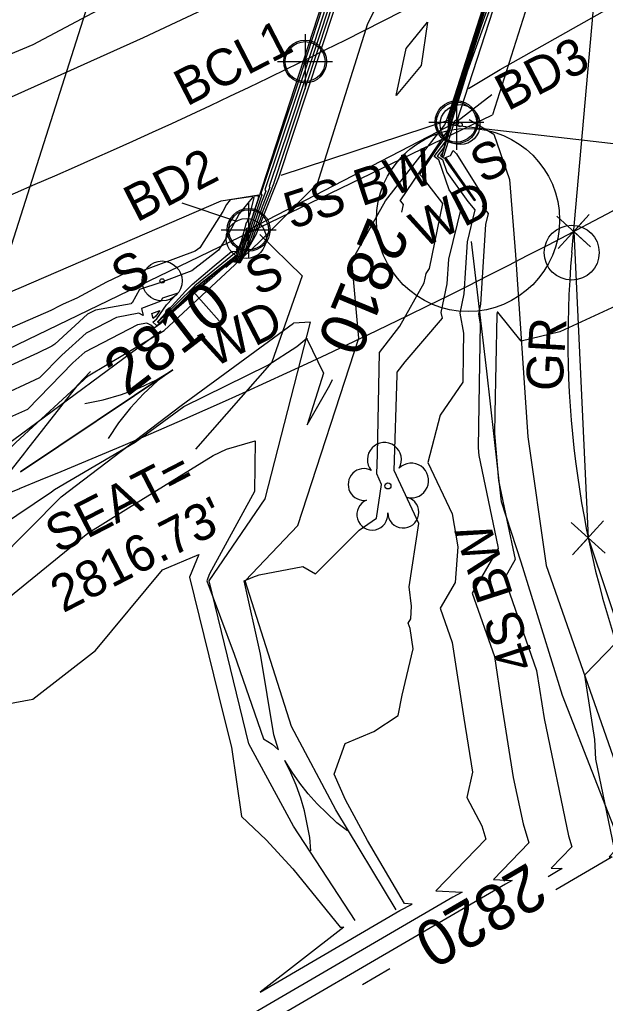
# Model space of a CAD drawing. Extents: x 1284446 to 1285480, y 969739 to 970628.
# Drawn here: x 1284857.4 to 1284921.4, y 970083.4 to 970190.8 of the extents above; entities that cross this region are included whole.
import ezdxf

# ---------------------------------------------------------------- set-up
doc = ezdxf.new("R2010")
doc.units = 0
for name, color, linetype in [('Cogo Default Point CELL', 7, 'Continuous'), ('Default', 7, 'Continuous'), ('Exist Horizontal Alignment', 7, 'Continuous'), ('Exist Horizontal Alignment Point', 7, 'Continuous'), ('Exist Hydro Jurisdictional Stream or Body of Water', 7, 'Continuous'), ('Exist Hydro River Flow Arrow CELL', 7, 'Continuous'), ('Exist Hydro Stream Flow Arrow CELL', 7, 'Continuous'), ('Exist Other Culture Fence Line', 7, 'Continuous'), ('Exist Other Culture Fence Line Text', 7, 'Continuous'), ('Exist Other Culture Located Object CELL', 7, 'Continuous'), ('Exist Other Culture Located Object Leader', 7, 'Continuous'), ('Exist Other Culture Located Object Text', 7, 'Continuous'), ('Exist Other Culture Sign CELL', 7, 'Continuous'), ('Exist Other Culture Sign Text', 7, 'Continuous'), ('Exist Property Corner CELL', 7, 'Continuous'), ('Exist Property Line', 7, 'Continuous'), ('Exist Right of Way Line', 7, 'Continuous'), ('Exist Roads EOP', 7, 'Continuous'), ('Exist Roads Soil', 7, 'Continuous'), ('Exist Roads Soil Text', 7, 'Continuous'), ('Exist Structure Major Bridge WW', 7, 'Continuous'), ('Exist Structure Major Bridge WW Leader', 7, 'Continuous'), ('Exist Structure Major Bridge WW Text', 7, 'Continuous'), ('Exist Structure Major Deck Tunnel Box Culvert', 7, 'Continuous'), ('Exist Structure Minor Head and End Wall', 7, 'Continuous'), ('Exist Vegetation Tree CELL', 7, 'Continuous')]:
    doc.layers.add(name, color=color, linetype=linetype)

msp = doc.modelspace()

# ---------------------------------------------------------------- linework, layer by layer
at = {"layer": 'Cogo Default Point CELL'}
for points in [[(1284888.59, 970189.26), (1284888.59, 970186.26)], [(1284885.59, 970186.26), (1284888.59, 970186.26)], [(1284888.59, 970186.26), (1284891.59, 970186.26)], [(1284888.59, 970186.26), (1284888.59, 970183.26)], [(1284905.12, 970182.64), (1284905.12, 970179.64)], [(1284902.12, 970179.64), (1284905.12, 970179.64)], [(1284905.12, 970179.64), (1284908.12, 970179.64)], [(1284905.12, 970179.64), (1284905.12, 970176.64)], [(1284882.42, 970170.89), (1284882.42, 970167.89)], [(1284879.42, 970167.89), (1284882.42, 970167.89)], [(1284882.42, 970167.89), (1284885.42, 970167.89)], [(1284882.42, 970167.89), (1284882.42, 970164.89)]]:
    msp.add_lwpolyline(points, dxfattribs=at)
for centre in [(1284888.59, 970186.26), (1284905.12, 970179.64), (1284882.42, 970167.89)]:
    msp.add_circle(centre, 2.34, dxfattribs=at)
at = {"layer": 'Default'}
for points in [[(1284899.15, 970169.83), (1284899.32, 970170.65), (1284899.03, 970171.02), (1284898.99, 970171.06), (1284903.87, 970178.3), (1284904.15, 970178.67), (1284904.24, 970178.96), (1284904.28, 970180.22), (1284904.39, 970180.56), (1284912.25, 970204.98)], [(1284911.74, 970201.12), (1284907.81, 970190.18), (1284905.23, 970182.15), (1284904.46, 970179.62), (1284904.44, 970179.21), (1284903.74, 970176.89), (1284903.02, 970175.95), (1284903.3, 970175.74), (1284903.58, 970175.58), (1284904.07, 970174.18), (1284906.37, 970170.99), (1284907.13, 970170.07), (1284906.29, 970166.6), (1284905.93, 970160.89), (1284905.49, 970158.78), (1284905.9, 970156.62), (1284905.85, 970154.4), (1284905.82, 970151.27), (1284903.33, 970147.65), (1284902.01, 970142.5), (1284904.66, 970136.9), (1284905.26, 970133.29), (1284904.97, 970129.39), (1284903.35, 970126.59), (1284904.66, 970122.84), (1284905.91, 970114.58), (1284906.86, 970108.69), (1284906.26, 970105.93), (1284907.88, 970102.82), (1284908.31, 970101.38), (1284902.87, 970095.74), (1284905.74, 970095.58), (1284904.71, 970095.03), (1284857.93, 970067.77)], [(1284856.22, 970127.75), (1284864.85, 970134.79), (1284870.66, 970138.38), (1284878.55, 970143.26), (1284880, 970143.94), (1284883.15, 970144.84), (1284883.05, 970139.32), (1284878.14, 970130.35), (1284877.86, 970129.58), (1284880.85, 970121.58), (1284884.03, 970112.32), (1284885, 970111.74), (1284885.68, 970111.11), (1284885.16, 970112.75), (1284883.72, 970121.57), (1284881.94, 970129.59), (1284882.9, 970129.97), (1284883.57, 970130.22), (1284888.34, 970131.13), (1284889.72, 970130.33), (1284894.51, 970135.09), (1284896.4, 970136.43), (1284896.95, 970140.1), (1284896.41, 970141.26), (1284896.48, 970143.35), (1284896.71, 970154.51), (1284898.92, 970157.37), (1284901.58, 970162.12), (1284901.82, 970163.13), (1284902.18, 970163.68), (1284903.64, 970170.75), (1284901.4, 970173.63), (1284901.12, 970173.94), (1284903.09, 970176.87), (1284904.01, 970178.07), (1284904.31, 970179.04), (1284904.34, 970180.02), (1284904.67, 970181.09), (1284910.77, 970200.05)], [(1284892.62, 970198.83), (1284888.83, 970187.06), (1284888.04, 970184.66), (1284883.74, 970171.87), (1284883.87, 970171.69), (1284883.75, 970171.38), (1284882.63, 970168.02), (1284882.57, 970167.88), (1284881.53, 970164.77), (1284881.39, 970164.52), (1284881.21, 970164.54), (1284881.15, 970164.55), (1284881.18, 970164.96), (1284881.59, 970166.18), (1284882.11, 970167.54), (1284882.26, 970168.07), (1284882.45, 970168.12), (1284883.44, 970171.1), (1284883.55, 970171.51), (1284883.38, 970171.62), (1284880.41, 970171.16), (1284880, 970170.65), (1284879.6, 970169.91), (1284877.09, 970165.93), (1284876.6, 970165.55), (1284870.45, 970163.26), (1284869.9, 970163.61), (1284866.9, 970162.18), (1284863.66, 970160.45), (1284862.16, 970159.79), (1284862.03, 970159.69), (1284861.8, 970159.58), (1284860.83, 970159.08), (1284851.5, 970155.03)], [(1284911.3, 970199.08), (1284906.34, 970185.25), (1284905.51, 970182.68), (1284904.51, 970179.42), (1284904.51, 970179.29), (1284903.6, 970176.3), (1284903.36, 970175.99), (1284903.45, 970175.92), (1284903.75, 970175.75), (1284903.82, 970175.73), (1284903.92, 970175.78), (1284904.48, 970176), (1284904.76, 970176.55), (1284905.12, 970176.2), (1284908.14, 970171.35), (1284908.18, 970171.1), (1284908.06, 970170.47), (1284907.93, 970170.46), (1284908.58, 970169.69), (1284908.29, 970168.49), (1284907.73, 970159.76), (1284907.51, 970158.7), (1284907.72, 970157.62), (1284907.59, 970151.12), (1284907.5, 970144.1), (1284907.57, 970143.27), (1284909.63, 970133.32), (1284909.67, 970133.12), (1284906.85, 970128.21), (1284909.26, 970121.32), (1284910.04, 970116.16), (1284911.33, 970108.11), (1284912.39, 970103.04), (1284913.02, 970100.96), (1284909.18, 970096.98), (1284911.2, 970096.86), (1284910.48, 970096.47), (1284873.73, 970075.07)], [(1284892.48, 970197.32), (1284889.57, 970188.3), (1284887.45, 970181.89), (1284884.21, 970172.25), (1284884.31, 970172.12), (1284883.82, 970170.9), (1284882.97, 970168.35), (1284882.75, 970167.79), (1284881.96, 970165.44), (1284881.41, 970164.45), (1284881.27, 970164.46), (1284881.03, 970164.52), (1284881.08, 970165.02), (1284877.43, 970162.18), (1284875.87, 970160.81), (1284872.68, 970157.68), (1284872.65, 970157.66), (1284872.51, 970157.82), (1284872.49, 970157.84), (1284872.52, 970157.87), (1284872.6, 970157.99), (1284875.53, 970161.2), (1284876.25, 970161.94), (1284878.67, 970163.96), (1284880.56, 970165.51), (1284881.08, 970165.57), (1284881.16, 970165.42), (1284881.64, 970166.65), (1284882.2, 970168.71), (1284882.27, 970168.73), (1284882.62, 970169.79), (1284883.03, 970171.41), (1284883.02, 970171.42), (1284882.8, 970171.39), (1284881.4, 970169.63), (1284880.01, 970167.06), (1284879.14, 970165.69), (1284876.22, 970163.41), (1284872.84, 970162.15), (1284870.5, 970161.39), (1284869.71, 970159.91), (1284869.59, 970159.86), (1284869.6, 970159.82), (1284869.58, 970159.83), (1284865.69, 970159.11), (1284864.84, 970158.67), (1284861.25, 970155.42), (1284860.92, 970155.18), (1284859.37, 970154.43), (1284853.43, 970151.74)], [(1284952.68, 970196.7), (1284945.69, 970190.22), (1284942.86, 970188.46), (1284935.48, 970181.51), (1284934.9, 970180.03), (1284930.07, 970174.35), (1284927.01, 970165.95), (1284926.01, 970164.12), (1284925.17, 970162.33), (1284923.72, 970147.16), (1284924.45, 970145.53), (1284925.3, 970134.22), (1284925.37, 970133.39), (1284927.01, 970127.29), (1284924.83, 970125.16), (1284919.12, 970119.27), (1284920.18, 970112.24), (1284920.31, 970110.09), (1284922.32, 970100.45), (1284922.43, 970100.11), (1284921.79, 970099.45), (1284922.13, 970099.44), (1284922.01, 970099.37), (1284915.97, 970095.85)], [(1284850.95, 970115.2), (1284858.84, 970116.67), (1284865.71, 970121.96), (1284873.03, 970130.76), (1284877, 970132.45), (1284875.98, 970129.99), (1284879.64, 970115.03), (1284880.55, 970111.4), (1284881.65, 970103.86), (1284884.33, 970101.3), (1284887.26, 970098.13), (1284892.41, 970091.77), (1284892.82, 970091.75), (1284883.68, 970084.68), (1284898.95, 970093.58), (1284900.28, 970094.29), (1284899.43, 970094.34), (1284895.41, 970101.22), (1284893.02, 970105.67), (1284891.76, 970108.48), (1284892.97, 970111.8), (1284896.09, 970113.14), (1284898.74, 970114.86), (1284899.2, 970117.09), (1284900.4, 970122.15), (1284900.07, 970124.36), (1284899.86, 970124.96), (1284900.12, 970125.41), (1284900.22, 970126.79), (1284899.96, 970128.93), (1284901, 970135.83), (1284898.3, 970141.63), (1284898.65, 970152.04), (1284898.66, 970152.36), (1284899.53, 970153.48), (1284903.58, 970158.26), (1284903.46, 970158.85), (1284904.12, 970162.01), (1284904.29, 970164.7), (1284905.69, 970170.46), (1284905.36, 970170.87), (1284904.34, 970172.27), (1284903.21, 970175.52), (1284903.14, 970175.56), (1284902.67, 970175.91), (1284903.87, 970177.48), (1284904.38, 970179.12), (1284904.4, 970179.82), (1284904.95, 970181.62), (1284909.29, 970195.11)], [(1284892.33, 970195.81), (1284890.31, 970189.55), (1284886.86, 970179.11), (1284884.68, 970172.64), (1284884.75, 970172.55), (1284883.89, 970170.41), (1284883.32, 970168.69), (1284882.93, 970167.7), (1284882.39, 970166.1), (1284881.42, 970164.38), (1284881.33, 970164.39), (1284880.92, 970164.48), (1284880.95, 970164.82), (1284878.49, 970162.9), (1284874.77, 970159.65), (1284872.75, 970157.66), (1284872.39, 970157.41), (1284872.3, 970157.51), (1284871.96, 970157.81), (1284872.41, 970158.18), (1284873.47, 970159.69), (1284874.12, 970160.4), (1284874.7, 970160.99), (1284873, 970160.44), (1284872.83, 970160.11), (1284870.73, 970159.32), (1284870.9, 970158.54), (1284870.45, 970158.78), (1284867.99, 970158.32), (1284864.69, 970156.61), (1284862.04, 970154.21), (1284859.6, 970151.72), (1284854.71, 970149.49)], [(1284847.39, 970183.34), (1284858.91, 970188.12), (1284871.31, 970194.74)], [(1284892.18, 970194.3), (1284891.05, 970190.79), (1284886.27, 970176.33), (1284885.16, 970173.02), (1284885.19, 970172.97), (1284883.97, 970169.92), (1284883.67, 970169.02), (1284883.11, 970167.62), (1284882.82, 970166.76), (1284881.44, 970164.31), (1284881.39, 970164.31), (1284880.8, 970164.44), (1284880.82, 970164.61), (1284879.56, 970163.63), (1284873.67, 970158.49), (1284872.82, 970157.65), (1284872.12, 970157.15), (1284872.09, 970157.2), (1284871.76, 970157.49), (1284871.32, 970157.72), (1284870.3, 970157.53), (1284864.54, 970154.54), (1284863.24, 970153.36), (1284858.27, 970148.29), (1284855.99, 970147.25)], [(1284891.79, 970192.04), (1284885.68, 970173.56), (1284885.63, 970173.4), (1284885.63, 970173.4), (1284884.04, 970169.44), (1284884.01, 970169.35), (1284883.28, 970167.53), (1284883.25, 970167.43), (1284881.45, 970164.24), (1284881.45, 970164.24), (1284880.68, 970164.4), (1284880.68, 970164.41), (1284880.62, 970164.36), (1284879.94, 970163.77)], [(1284898.52, 970182.56), (1284899.63, 970187.69), (1284901.94, 970190.57), (1284901.27, 970185.83), (1284898.52, 970182.56)], [(1284881.23, 970166.03), (1284881.06, 970165.71), (1284881.13, 970165.72), (1284881.14, 970165.72), (1284881.16, 970165.77), (1284881.23, 970166.03)], [(1284923.51, 970160.05), (1284916.41, 970156.77), (1284912.2, 970155.75), (1284909.64, 970158.9), (1284909.55, 970158.89), (1284909.54, 970158.64), (1284909.53, 970158.63), (1284909.54, 970158.61), (1284909.32, 970147.85), (1284909.29, 970145.64), (1284909.7, 970140.53), (1284910.61, 970136.18), (1284911.54, 970131.92), (1284910.35, 970129.84), (1284913.86, 970119.8), (1284914.17, 970117.74), (1284914.68, 970114.53), (1284917.36, 970101.75), (1284917.72, 970100.53), (1284915.48, 970098.22), (1284916.66, 970098.15), (1284916.24, 970097.92), (1284915.12, 970097.27)], [(1284871.99, 970158.23), (1284871.86, 970158.77), (1284872.73, 970159.1), (1284872.29, 970158.48), (1284871.99, 970158.23)], [(1284865.15, 970152.41), (1284863.74, 970150.95), (1284858.15, 970143.83), (1284857.93, 970143.55), (1284851.44, 970135.29), (1284845.39, 970127.31), (1284855.19, 970135.46), (1284860.88, 970139.28), (1284861.21, 970139.54), (1284870.02, 970144.7), (1284875.33, 970148.62), (1284884.51, 970153.12), (1284887.68, 970155.16), (1284888.77, 970156.05), (1284888.78, 970156.01), (1284890.6, 970152.24), (1284888.81, 970146.6), (1284891.3, 970150.92), (1284891.58, 970151.55)], [(1284897.84, 970087.2), (1284894.85, 970085.46)]]:
    msp.add_lwpolyline(points, dxfattribs=at)
at = {"layer": 'Exist Horizontal Alignment'}
msp.add_line((1284917.71, 970165.4), (1284921.13, 970203.64), dxfattribs=at)
for centre, radius, start, end in [((1284607.88, 970757.2), 636.05, 292.00278, 305.45278), ((1285024.14, 970155.89), 106.85, 174.8913, 201.0367)]:
    msp.add_arc(centre, radius, start, end, dxfattribs=at)
at = {"layer": 'Exist Horizontal Alignment Point'}
msp.add_circle((1284917.71, 970165.4), 3, dxfattribs=at)
at = {"layer": 'Exist Hydro Jurisdictional Stream or Body of Water'}
for points in [[(1284873.19, 970156.9), (1284883.51, 970166.48), (1284889.94, 970172.96), (1284895.44, 970190.43), (1284903.3, 970205.95), (1284913.73, 970232), (1284923.66, 970254.25), (1284941.01, 970272.57), (1284958.16, 970292.53), (1284979.26, 970313.17), (1284998.61, 970327.4), (1285021.77, 970343.41), (1285038.64, 970357.96), (1285060.69, 970382.43), (1285077.07, 970403.68), (1285083.99, 970417.36), (1285093.67, 970433.2), (1285120.38, 970455.77)], [(1284898.55, 970093.67), (1284891.93, 970104.57), (1284887.09, 970113.68), (1284882.06, 970129.58), (1284887.8, 970135.61), (1284894.46, 970156.08), (1284893.69, 970164.51), (1284897.37, 970171.05), (1284903.86, 970179.35), (1284904.34, 970180.6), (1284915.98, 970216.96), (1284921.11, 970228.41), (1284932.56, 970248.17), (1284947.31, 970266.45), (1284964.91, 970285.06), (1284987.35, 970303.2), (1285005.06, 970315.3), (1285028.92, 970334.49), (1285047.82, 970349.99), (1285069.69, 970374.61), (1285084.31, 970397.98), (1285093.11, 970411.54), (1285103.27, 970427.02), (1285126.73, 970448.14)], [(1284608.58, 970014.06), (1284652.45, 970028.03), (1284689.07, 970040.96), (1284720.23, 970048.49), (1284751.74, 970066.17), (1284777.43, 970074.66), (1284799.45, 970086.45), (1284820.82, 970098.72), (1284840.81, 970117.42), (1284861.95, 970138.73), (1284875.04, 970148.73), (1284887.31, 970157.71)], [(1284894.05, 970092.48), (1284887.33, 970102.8), (1284882.46, 970111.77), (1284878.1, 970129.59), (1284884.22, 970138.52), (1284889.17, 970157.81), (1284887.31, 970157.71)], [(1284608.31, 970022.37), (1284646.2, 970034.88), (1284690.96, 970050.11), (1284715.91, 970057.86), (1284748.8, 970074.52), (1284773.24, 970082.29), (1284795.23, 970094.54), (1284815.77, 970108.56), (1284836.54, 970123.66), (1284856.99, 970144.69), (1284864.89, 970151.94), (1284873.19, 970156.9)]]:
    msp.add_lwpolyline(points, dxfattribs=at)
at = {"layer": 'Exist Hydro River Flow Arrow CELL'}
msp.add_line((1284865.82, 970147.03), (1284865.82, 970147.03), dxfattribs=at)
msp.add_lwpolyline([(1284864.54, 970148.93), (1284866.55, 970149.33), (1284868.55, 970149.9), (1284870.5, 970150.64), (1284872.38, 970151.52), (1284874.13, 970152.6), (1284857.51, 970141.47), (1284874.13, 970152.6), (1284872.46, 970151.39), (1284870.94, 970149.99), (1284869.51, 970148.46), (1284868.22, 970146.83), (1284867.09, 970145.13)], dxfattribs=at)
at = {"layer": 'Exist Hydro Stream Flow Arrow CELL'}
msp.add_line((1284888.8, 970105.57), (1284888.8, 970105.57), dxfattribs=at)
for points in [[(1284893.22, 970102.29), (1284892.05, 970103.17), (1284890.96, 970104.2), (1284889.89, 970105.22), (1284888.94, 970106.31), (1284888.02, 970107.48), (1284887.16, 970108.7), (1284886.39, 970109.95)], [(1284889.21, 970100.08), (1284889.09, 970101.54), (1284888.81, 970103.02), (1284888.51, 970104.46), (1284888.11, 970105.85), (1284887.61, 970107.25), (1284887.03, 970108.63), (1284886.39, 970109.95)]]:
    msp.add_lwpolyline(points, dxfattribs=at)
at = {"layer": 'Exist Other Culture Fence Line'}
msp.add_line((1284904.43, 970179.89), (1284885.95, 970173.83), dxfattribs=at)
for points in [[(1284912.2, 970131.6), (1284910.05, 970138.19), (1284908.45, 970152.46), (1284906.77, 970166.63)], [(1284601.96, 970038.43), (1284640.3, 970053.54), (1284684.75, 970071.66), (1284706.29, 970079.75), (1284740.35, 970092.84), (1284765.34, 970102.18), (1284786.69, 970110.23), (1284807.57, 970118.44), (1284832.39, 970127.91), (1284856.77, 970145.02), (1284872.83, 970156.87)], [(1284923.19, 970100.46), (1284916.7, 970117.07), (1284912.2, 970131.6)]]:
    msp.add_lwpolyline(points, dxfattribs=at)
at = {"layer": 'Exist Other Culture Located Object CELL'}
for centre, radius in [((1284888.59, 970186.26), 2.18), ((1284888.59, 970186.26), 0.24), ((1284905.12, 970179.64), 2.18), ((1284905.12, 970179.64), 0.24), ((1284882.42, 970167.89), 2.18), ((1284882.42, 970167.89), 0.24)]:
    msp.add_circle(centre, radius, dxfattribs=at)
at = {"layer": 'Exist Other Culture Located Object Leader'}
for p, q in [((1284905.15, 970179.71), (1284908.99, 970182.67)), ((1284904.56, 970179.35), (1284940.97, 970175.17)), ((1284880.92, 970168.89), (1284875.16, 970170.79))]:
    msp.add_line(p, q, dxfattribs=at)
msp.add_lwpolyline([(1284883.63, 970167.4), (1284888.26, 970162.88), (1284884.97, 970153.46), (1284876.61, 970143.96)], dxfattribs=at)
at = {"layer": 'Exist Other Culture Located Object Text'}
for p, q in [((1284921.6, 970219.82), (1284909.05, 970180.44)), ((1284864.82, 970192.39), (1284852.28, 970153.01)), ((1284852.28, 970153.01), (1284909.05, 970180.44))]:
    msp.add_line(p, q, dxfattribs=at)
msp.add_circle((1284906.38, 970168.97), 10, dxfattribs=at)
at = {"layer": 'Exist Other Culture Sign CELL'}
for centre, radius in [((1284905.51, 970179.38), 2.18), ((1284905.51, 970179.38), 0.24), ((1284882.16, 970166.95), 2.18), ((1284882.16, 970166.95), 0.24), ((1284872.98, 970162.31), 2.18), ((1284872.98, 970162.31), 0.24)]:
    msp.add_circle(centre, radius, dxfattribs=at)
at = {"layer": 'Exist Property Corner CELL'}
for p, q in [((1284917.92, 970167.71), (1284917.92, 970167.71)), ((1284919.5, 970134.26), (1284919.5, 970134.26))]:
    msp.add_line(p, q, dxfattribs=at)
for points in [[(1284916.07, 970169.39), (1284919.77, 970166.03), (1284917.92, 970167.71), (1284919.6, 970169.56), (1284916.24, 970165.86)], [(1284921.35, 970132.58), (1284917.65, 970135.95), (1284919.5, 970134.26), (1284917.81, 970132.41), (1284921.18, 970136.11)]]:
    msp.add_lwpolyline(points, dxfattribs=at)
at = {"layer": 'Exist Property Line'}
for p, q in [((1284917.92, 970167.71), (1284919.5, 970134.26)), ((1284919.5, 970134.26), (1284945.62, 970056.2))]:
    msp.add_line(p, q, dxfattribs=at)
at = {"layer": 'Exist Right of Way Line'}
msp.add_line((1284603.06, 970036.88), (1284857.42, 970139.66), dxfattribs=at)
msp.add_arc((1284607.88, 970757.2), 666.05, 292.00278, 305.45278, dxfattribs=at)
at = {"layer": 'Exist Roads EOP'}
for points in [[(1284906.42, 970183.31), (1284909.89, 970185.39), (1284925.09, 970194), (1284944.45, 970205.72), (1284965.49, 970219.25), (1284989.1, 970235.63), (1285013.02, 970252.46), (1285035.6, 970268.52), (1285058.25, 970284.75), (1285080.34, 970300.38), (1285103.05, 970316.58), (1285125.6, 970332.83), (1285149.35, 970349.65), (1285172.35, 970366.09), (1285195.52, 970382.27)], [(1284588.17, 970073.97), (1284609.91, 970082.54), (1284630.17, 970090.65), (1284654.44, 970100.5), (1284678.03, 970109.93), (1284701.92, 970119.24), (1284725.51, 970128.63), (1284750.96, 970139.34), (1284775.61, 970149.46), (1284801.89, 970159.77), (1284826.13, 970169.58), (1284850.02, 970179.49), (1284870.96, 970188.88), (1284892.26, 970198.92), (1284892.63, 970199.46)], [(1284594.23, 970054.93), (1284616.52, 970063.71), (1284637.53, 970072.23), (1284661.54, 970081.97), (1284684.2, 970091.02), (1284708.29, 970100.77), (1284732.61, 970110.68), (1284757.85, 970120.85), (1284782.44, 970130.77), (1284809.22, 970141.4), (1284833.63, 970151.55), (1284857.38, 970161.54), (1284879.44, 970171.07), (1284883.53, 970171.7)]]:
    msp.add_lwpolyline(points, dxfattribs=at)
at = {"layer": 'Exist Roads Soil'}
msp.add_lwpolyline([(1284906.49, 970179.93), (1284909.19, 970178.32), (1284910.9, 970173.4), (1284911.57, 970165.15), (1284912.9, 970145.3), (1284914.91, 970131.26), (1284924.98, 970102.56)], dxfattribs=at)
at = {"layer": 'Exist Structure Major Bridge WW'}
for points in [[(1284904.02, 970175.68), (1284903.86, 970175.62), (1284907.05, 970171.08), (1284907.21, 970171.14), (1284904.02, 970175.68)], [(1284881.05, 970165.45), (1284876.55, 970161.78), (1284872.53, 970157.84), (1284872.67, 970157.68), (1284876.67, 970161.65), (1284881.18, 970165.19), (1284881.05, 970165.45)]]:
    msp.add_lwpolyline(points, dxfattribs=at)
at = {"layer": 'Exist Structure Major Bridge WW Leader'}
msp.add_line((1284876.38, 970161.15), (1284879.21, 970157.94), dxfattribs=at)
at = {"layer": 'Exist Structure Major Deck Tunnel Box Culvert'}
msp.add_lwpolyline([(1284893.52, 970202.02), (1284916.14, 970213.69), (1284905.12, 970179.64), (1284882.42, 970167.89), (1284893.52, 970202.02)], dxfattribs=at)
at = {"layer": 'Exist Structure Minor Head and End Wall'}
for points in [[(1284904.54, 970179.32), (1284903.53, 970176.01), (1284903.75, 970175.94), (1284904.83, 970179.48)], [(1284882.26, 970167.78), (1284881.19, 970164.57), (1284881.39, 970164.55), (1284882.5, 970167.89)]]:
    msp.add_lwpolyline(points, dxfattribs=at)
at = {"layer": 'Exist Vegetation Tree CELL'}
msp.add_line((1284897.64, 970139.93), (1284897.64, 970139.93), dxfattribs=at)
msp.add_circle((1284897.64, 970139.93), 0.326, dxfattribs=at)
for centre, radius, start, end in [((1284897.25, 970142.81), 1.86, 330.1651, 219.7134), ((1284900.18, 970140.52), 1.9, 257.1011, 134.1999), ((1284895.03, 970140.09), 1.73, 62.6636, 279.3457), ((1284895.93, 970136.81), 1.69, 111.5671, 6.231), ((1284899.31, 970137.04), 1.7, 181.2822, 74.56)]:
    msp.add_arc(centre, radius, start, end, dxfattribs=at)

# ---------------------------------------------------------------- texts
at = {"layer": 'Default'}
for s, rotation, p in [('2810', 247.5059, (1284895.53, 970169.46)), ('2810', 37.5146, (1284869.13, 970149.6)), ('2820', 210.2246, (1284912.96, 970098.9))]:
    msp.add_text(s, height=5, rotation=rotation, dxfattribs=at).set_placement(p)
at = {"layer": 'Exist Other Culture Fence Line Text'}
for s, rotation, p in [('5S BW', 18.1509, (1284887.11, 970167.93)), ('4S BW', 108.0948, (1284913.84, 970120.4))]:
    msp.add_text(s, height=4, rotation=rotation, dxfattribs=at).set_placement(p)
at = {"layer": 'Exist Other Culture Located Object Text'}
for s, p in [('BCL1', (1284875.66, 970181.32)), ('BD3', (1284910.71, 970180.81)), ('BD2', (1284870.18, 970168.66)), ('SEAT=', (1284861.59, 970132.48)), ("2816.73'", (1284862.16, 970126.02))]:
    msp.add_text(s, height=4, rotation=27.3235, dxfattribs=at).set_placement(p)
at = {"layer": 'Exist Other Culture Sign Text'}
for p in [(1284907.99, 970172.86), (1284868.79, 970160.69), (1284883.42, 970160.58)]:
    msp.add_text('S', height=4, rotation=27.3235, dxfattribs=at).set_placement(p)
at = {"layer": 'Exist Roads Soil Text'}
msp.add_text('GR', height=4, rotation=86.5707, dxfattribs=at).set_placement((1284916.67, 970150.19))
at = {"layer": 'Exist Structure Major Bridge WW Text'}
for p in [(1284901.42, 970165.82), (1284878.59, 970152.78)]:
    msp.add_text('WD', height=4, rotation=27.3235, dxfattribs=at).set_placement(p)

doc.saveas('drawing.dxf')
